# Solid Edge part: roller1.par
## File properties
Author: jmrobins
Template: sync iso part.par
Last saved by: mokuno
Revision: 11
Application: Solid Edge
Username: jmrobins
文書内容のタイプ: 0
Accuracy: 0.990
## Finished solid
Body 1: solid body, 9 faces, 8 edges, 0 vertices.
  Faces by surface: plane 4, cylinder 3, cone 2
  Edges by curve: circle 8
Bounding box of the edges (mm): 260.000 x 80.000 x 80.000, from (-130, -40, -40) to (130, 40, 40).
Cylindrical faces by radius (mm): R17.5 x2, R40 x1
Conical faces (half-angle, radius in mm at the cone's reference point): 45 deg R17.5 x2
Planar faces by outward normal: +x 2, -x 2
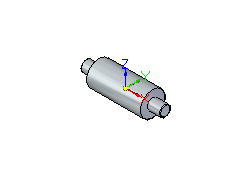
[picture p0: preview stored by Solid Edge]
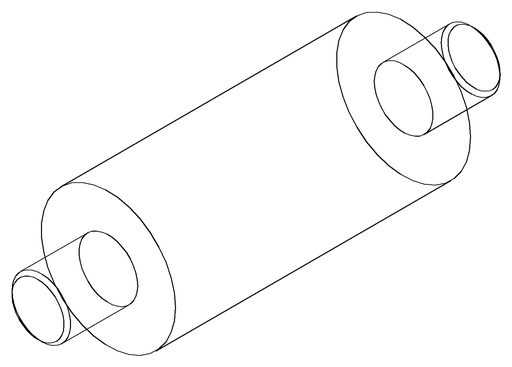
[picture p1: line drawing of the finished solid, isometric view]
